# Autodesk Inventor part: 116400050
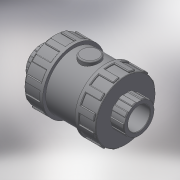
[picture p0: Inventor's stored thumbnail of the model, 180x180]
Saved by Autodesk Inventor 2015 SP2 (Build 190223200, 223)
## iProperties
Created: 2017-11
Part Number: 116400050
Material: Generic
Description: PLASSON FOOT VALVE CEM PVC 50
Document SubType Name: Modeling
Designer: KIM
Density: 1 g/cm^3
Appearance: Default
Author: KIM
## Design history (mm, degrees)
derived "116400 - 116000.ipt"
feature "Solid1::116400 - 116000.ipt"
tag "TaggingFeature1"
body "Solid1"
other parameters: "d0" = 142, "d2" = 96, "d3" = 31, "d5" = 21.7, "d8" = 86.4, "d13" = 1.5, "d23" = 31, "d24" = 92.16, "d25" = 1, "d26" = 1.5, "d27" = 14.4, "d28" = 7.2, "d29" = 23.25, "d30" = 0, "d35" = 1.5, "d39" = 48, "d45" = 360 deg, "d47" = 1, "d50" = 48, "d51" = 28.8, "d53" = 0, "d54" = 1.92, "d57" = 5, "d59" = 0, "d60" = 1.5, "d62" = 360 deg, "l_" = 31, "H_" = 142, "K_" = 96
